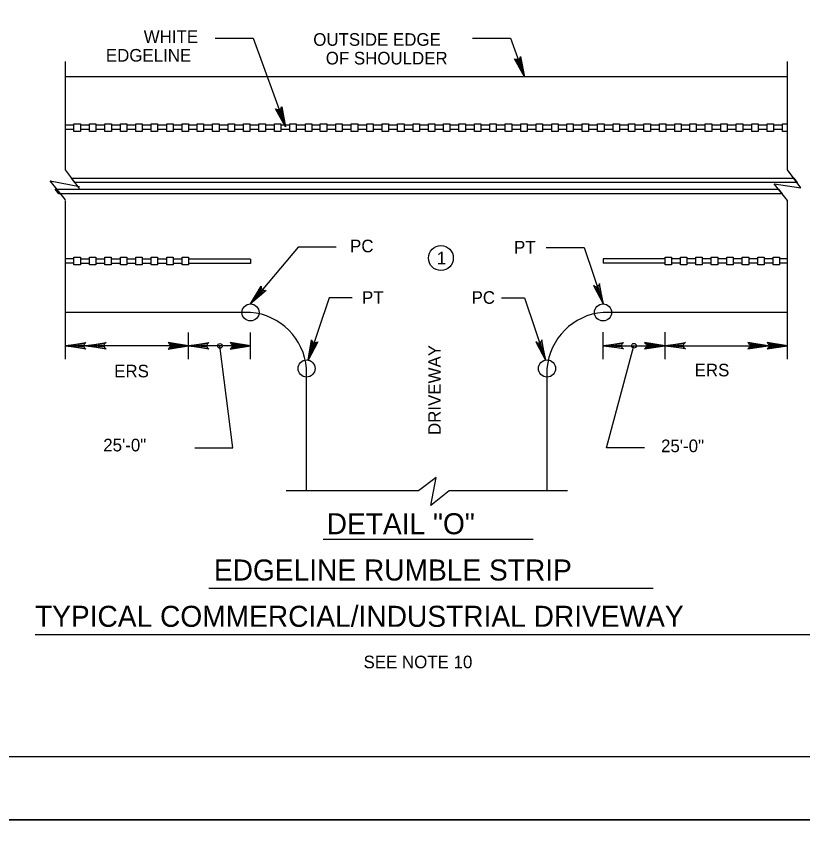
# Model space of a CAD drawing. Extents: x 632008 to 634206, y 294231 to 297795.
# Drawn here: x 632240.2 to 632427, y 296005.1 to 296203.4 of the extents above; entities that cross this region are included whole.
import ezdxf

# ---------------------------------------------------------------- set-up
doc = ezdxf.new("R2010")
doc.units = 0
for name, color, linetype in [('1', 7, 'Continuous'), ('3', 7, 'Continuous'), ('Level 2', 7, 'Continuous'), ('PLT-BNDY', 7, 'Continuous')]:
    doc.layers.add(name, color=color, linetype=linetype)

msp = doc.modelspace()

# ---------------------------------------------------------------- linework, layer by layer
at = {"layer": '1'}
for p, q in [((632295.81, 296145.82), (632295.81, 296144.8)), ((632379.61, 296145.91), (632379.61, 296144.9)), ((632313.08, 296079.29), (632362.95, 296079.29)), ((632285.89, 296067.61), (632391.48, 296067.61)), ((632244.66, 296056.61), (632433.76, 296056.61))]:
    msp.add_line(p, q, dxfattribs=at)
msp.add_lwpolyline([(632833.86, 296027.62), (632833.86, 296591.62), (632047.86, 296591.62), (632047.86, 296027.62), (632833.86, 296027.62), (632833.86, 296053.98), (632633.86, 296053.98), (632633.86, 296118.66), (632833.86, 296118.66), (632833.86, 296147.62), (632633.86, 296147.62), (632633.86, 296027.62), (632712.66, 296027.62), (632712.66, 296053.98), (632712.66, 296027.62), (632789.66, 296027.62), (632789.66, 296053.98), (632789.66, 296041.66), (632833.86, 296041.66)], dxfattribs=at)
for points in [[(632253.3, 296165.06), (632424.94, 296165.06), (632425.73, 296164), (632254.09, 296164)], [(632422.15, 296161.36), (632250.27, 296161.36), (632249.41, 296162.42), (632421.3, 296162.42)]]:
    msp.add_lwpolyline(points, close=True, dxfattribs=at)
at = {"layer": '3'}
for points in [[(632319.95, 296136.61), (632314.48, 296136.61), (632309.52, 296121.84)], [(632355.46, 296136.61), (632360.92, 296136.61), (632365.89, 296121.84)], [(632311.53, 296126.02), (632311.16, 296125.96), (632309.52, 296121.84), (632311.53, 296126.02), (632311.8, 296126.18), (632309.52, 296121.84), (632310.72, 296126.11), (632310.46, 296126.36), (632309.52, 296121.84), (632310.33, 296126.67), (632310.46, 296126.36)], [(632363.87, 296126.02), (632364.24, 296125.96), (632365.89, 296121.84), (632363.87, 296126.02), (632363.61, 296126.18), (632365.89, 296121.84), (632364.68, 296126.11), (632364.94, 296126.36), (632365.89, 296121.84), (632365.07, 296126.67), (632364.94, 296126.36)]]:
    msp.add_lwpolyline(points, dxfattribs=at)
for centre, radius in [((632341.06, 296146.08), 2.95), ((632309.13, 296119.85), 2.03), ((632366.28, 296119.85), 2.03)]:
    msp.add_circle(centre, radius, dxfattribs=at)
at = {"layer": 'Level 2'}
for p, q in [((632251.81, 296167.04), (632251.82, 296192.79)), ((632423.46, 296167.04), (632423.46, 296192.79)), ((632423.46, 296189.15), (632251.81, 296189.15)), ((632253.85, 296177.63), (632251.81, 296177.63)), ((632257.52, 296177.63), (632255.38, 296177.63)), ((632261.2, 296177.63), (632259.05, 296177.63)), ((632264.87, 296177.63), (632262.73, 296177.63)), ((632268.54, 296177.63), (632266.4, 296177.63)), ((632272.21, 296177.63), (632270.07, 296177.63)), ((632275.89, 296177.63), (632273.74, 296177.63)), ((632279.56, 296177.63), (632277.42, 296177.63)), ((632283.13, 296177.63), (632281.09, 296177.63)), ((632286.8, 296177.63), (632284.66, 296177.63)), ((632290.47, 296177.63), (632288.33, 296177.63)), ((632294.14, 296177.63), (632292, 296177.63)), ((632297.82, 296177.63), (632295.67, 296177.63)), ((632301.49, 296177.63), (632299.35, 296177.63)), ((632305.16, 296177.63), (632303.02, 296177.63)), ((632308.84, 296177.63), (632306.69, 296177.63)), ((632312.4, 296177.63), (632310.37, 296177.63)), ((632316.07, 296177.63), (632313.93, 296177.63)), ((632319.75, 296177.63), (632317.6, 296177.63)), ((632323.42, 296177.63), (632321.28, 296177.63)), ((632327.09, 296177.63), (632324.95, 296177.63)), ((632330.76, 296177.63), (632328.62, 296177.63)), ((632334.44, 296177.63), (632332.3, 296177.63)), ((632338.11, 296177.63), (632335.97, 296177.63)), ((632341.68, 296177.63), (632339.64, 296177.63)), ((632345.35, 296177.63), (632343.21, 296177.63)), ((632349.02, 296177.63), (632346.88, 296177.63)), ((632352.69, 296177.63), (632350.55, 296177.63)), ((632356.37, 296177.63), (632354.23, 296177.63)), ((632360.04, 296177.63), (632357.9, 296177.63)), ((632363.71, 296177.63), (632361.57, 296177.63)), ((632367.39, 296177.63), (632365.24, 296177.63)), ((632370.95, 296177.63), (632368.92, 296177.63)), ((632374.62, 296177.63), (632372.48, 296177.63)), ((632378.3, 296177.63), (632376.16, 296177.63)), ((632381.97, 296177.63), (632379.83, 296177.63)), ((632385.64, 296177.63), (632383.5, 296177.63)), ((632389.32, 296177.63), (632387.17, 296177.63)), ((632392.99, 296177.63), (632390.85, 296177.63)), ((632396.66, 296177.63), (632394.52, 296177.63)), ((632400.23, 296177.63), (632398.19, 296177.63)), ((632403.9, 296177.63), (632401.76, 296177.63)), ((632407.57, 296177.63), (632405.43, 296177.63)), ((632411.25, 296177.63), (632409.1, 296177.63)), ((632414.92, 296177.63), (632412.78, 296177.63)), ((632418.59, 296177.63), (632416.45, 296177.63)), ((632422.26, 296177.63), (632420.12, 296177.63)), ((632253.85, 296176.61), (632251.81, 296176.61)), ((632257.52, 296176.61), (632255.38, 296176.61)), ((632261.2, 296176.61), (632259.05, 296176.61)), ((632264.87, 296176.61), (632262.73, 296176.61)), ((632268.54, 296176.61), (632266.4, 296176.61)), ((632272.21, 296176.61), (632270.07, 296176.61)), ((632275.89, 296176.61), (632273.74, 296176.61)), ((632279.56, 296176.61), (632277.42, 296176.61)), ((632283.13, 296176.61), (632281.09, 296176.61)), ((632286.8, 296176.61), (632284.66, 296176.61)), ((632290.47, 296176.61), (632288.33, 296176.61)), ((632294.14, 296176.61), (632292, 296176.61)), ((632297.82, 296176.61), (632295.67, 296176.61)), ((632301.49, 296176.61), (632299.35, 296176.61)), ((632305.16, 296176.61), (632303.02, 296176.61)), ((632308.84, 296176.61), (632306.69, 296176.61)), ((632312.4, 296176.61), (632310.37, 296176.61)), ((632316.07, 296176.61), (632313.93, 296176.61)), ((632319.75, 296176.61), (632317.6, 296176.61)), ((632323.42, 296176.61), (632321.28, 296176.61)), ((632327.09, 296176.61), (632324.95, 296176.61)), ((632330.76, 296176.61), (632328.62, 296176.61)), ((632334.44, 296176.61), (632332.3, 296176.61)), ((632338.11, 296176.61), (632335.97, 296176.61)), ((632341.68, 296176.61), (632339.64, 296176.61)), ((632345.35, 296176.61), (632343.21, 296176.61)), ((632349.02, 296176.61), (632346.88, 296176.61)), ((632352.69, 296176.61), (632350.55, 296176.61)), ((632356.37, 296176.61), (632354.23, 296176.61)), ((632360.04, 296176.61), (632357.9, 296176.61)), ((632363.71, 296176.61), (632361.57, 296176.61)), ((632367.39, 296176.61), (632365.24, 296176.61)), ((632370.95, 296176.61), (632368.92, 296176.61)), ((632374.62, 296176.61), (632372.48, 296176.61)), ((632378.3, 296176.61), (632376.16, 296176.61)), ((632381.97, 296176.61), (632379.83, 296176.61)), ((632385.64, 296176.61), (632383.5, 296176.61)), ((632389.32, 296176.61), (632387.17, 296176.61)), ((632392.99, 296176.61), (632390.85, 296176.61)), ((632396.66, 296176.61), (632394.52, 296176.61)), ((632400.23, 296176.61), (632398.19, 296176.61)), ((632403.9, 296176.61), (632401.76, 296176.61)), ((632407.57, 296176.61), (632405.43, 296176.61)), ((632411.25, 296176.61), (632409.1, 296176.61)), ((632414.92, 296176.61), (632412.78, 296176.61)), ((632418.59, 296176.61), (632416.45, 296176.61)), ((632422.26, 296176.61), (632420.12, 296176.61)), ((632255.13, 296162.61), (632251.81, 296167.04)), ((632426.64, 296162.78), (632423.46, 296167.04)), ((632248.17, 296164.42), (632255.13, 296163.07)), ((632251.81, 296159.92), (632248.17, 296164.42)), ((632423.46, 296159.76), (632420.25, 296163.71)), ((632420.25, 296163.71), (632426.64, 296162.78)), ((632251.81, 296122.05), (632251.81, 296159.76)), ((632423.46, 296122.09), (632423.46, 296159.76)), ((632253.85, 296145.9), (632251.81, 296145.9)), ((632257.52, 296145.82), (632255.38, 296145.82)), ((632261.19, 296145.82), (632259.05, 296145.82)), ((632264.87, 296145.82), (632262.72, 296145.82)), ((632268.54, 296145.82), (632266.4, 296145.82)), ((632272.21, 296145.82), (632270.07, 296145.82)), ((632275.89, 296145.82), (632273.74, 296145.82)), ((632279.56, 296145.82), (632277.42, 296145.82)), ((632295.81, 296145.82), (632281.09, 296145.82)), ((632394.32, 296145.91), (632379.61, 296145.91)), ((632397.99, 296145.91), (632395.85, 296145.91)), ((632401.66, 296145.91), (632399.52, 296145.91)), ((632405.33, 296145.91), (632403.19, 296145.91)), ((632409.01, 296145.91), (632406.86, 296145.91)), ((632412.68, 296145.91), (632410.54, 296145.91)), ((632416.35, 296145.91), (632414.21, 296145.91)), ((632420.03, 296145.91), (632417.88, 296145.91)), ((632423.46, 296145.91), (632421.56, 296145.91)), ((632253.85, 296144.89), (632251.81, 296144.89)), ((632257.52, 296144.8), (632255.38, 296144.8)), ((632261.19, 296144.8), (632259.05, 296144.8)), ((632264.87, 296144.8), (632262.72, 296144.8)), ((632268.54, 296144.8), (632266.4, 296144.8)), ((632272.21, 296144.8), (632270.07, 296144.8)), ((632275.89, 296144.8), (632273.74, 296144.8)), ((632279.56, 296144.8), (632277.42, 296144.8)), ((632295.81, 296144.8), (632281.09, 296144.8)), ((632394.32, 296144.9), (632379.61, 296144.9)), ((632397.99, 296144.9), (632395.85, 296144.9)), ((632401.66, 296144.9), (632399.52, 296144.9)), ((632405.33, 296144.9), (632403.19, 296144.9)), ((632409.01, 296144.9), (632406.86, 296144.9)), ((632412.68, 296144.9), (632410.54, 296144.9)), ((632416.35, 296144.9), (632414.21, 296144.9)), ((632420.03, 296144.9), (632417.88, 296144.9)), ((632423.46, 296144.9), (632421.56, 296144.9)), ((632295.81, 296133.16), (632251.95, 296133.16)), ((632423.46, 296133.16), (632379.59, 296133.16)), ((632281.09, 296122.05), (632281.09, 296128.4)), ((632295.81, 296122.05), (632295.81, 296128.4)), ((632379.59, 296122.09), (632379.59, 296128.44)), ((632394.32, 296122.09), (632394.32, 296128.44)), ((632295.81, 296125.22), (632251.81, 296125.22)), ((632379.59, 296125.26), (632423.46, 296125.26)), ((632309.13, 296090.79), (632309.13, 296119.85)), ((632366.28, 296090.79), (632366.28, 296119.85)), ((632339.97, 296093.98), (632335.72, 296090.79)), ((632338.68, 296087.29), (632339.97, 296093.98)), ((632335.72, 296090.79), (632304.28, 296090.79)), ((632343, 296090.79), (632338.68, 296087.29)), ((632371.13, 296090.79), (632343, 296090.79))]:
    msp.add_line(p, q, dxfattribs=at)
for points in [[(632287.43, 296198.35), (632296.46, 296198.35), (632304.15, 296177.23)], [(632348.54, 296198.35), (632357.58, 296198.35), (632360.93, 296189.15)], [(632359.89, 296193.67), (632359.64, 296193.4), (632360.93, 296189.15), (632359.89, 296193.67), (632360, 296193.96), (632360.93, 296189.15), (632359.2, 296193.24), (632358.84, 296193.27), (632360.93, 296189.15), (632358.55, 296193.43), (632358.84, 296193.27)], [(632303.11, 296181.75), (632302.86, 296181.48), (632304.15, 296177.23), (632303.11, 296181.75), (632303.22, 296182.05), (632304.15, 296177.23), (632302.42, 296181.32), (632302.06, 296181.36), (632304.15, 296177.23), (632301.77, 296181.51), (632302.06, 296181.36)], [(632423.46, 296176.12), (632422.26, 296176.12), (632422.26, 296177.96), (632423.46, 296177.96)], [(632423.46, 296176.12), (632422.26, 296176.12), (632422.26, 296177.96), (632423.46, 296177.96)], [(632316.18, 296148.65), (632307.14, 296148.65), (632295.81, 296135.19)], [(632366.05, 296148.61), (632375.08, 296148.61), (632379.59, 296135.19)], [(632377.58, 296139.37), (632377.95, 296139.31), (632379.59, 296135.19), (632377.58, 296139.37), (632377.31, 296139.53), (632379.59, 296135.19), (632378.39, 296139.46), (632378.65, 296139.71), (632379.59, 296135.19), (632378.78, 296140.02), (632378.65, 296139.71)], [(632299.23, 296138.33), (632298.86, 296138.42), (632295.81, 296135.19), (632299.23, 296138.33), (632299.53, 296138.38), (632295.81, 296135.19), (632298.5, 296138.71), (632298.36, 296139.05), (632295.81, 296135.19), (632298.35, 296139.38), (632298.36, 296139.05)], [(632256.42, 296124.64), (632256.25, 296124.98), (632251.81, 296125.22), (632256.42, 296124.64), (632256.65, 296124.44), (632251.81, 296125.22), (632256.24, 296125.44), (632256.4, 296125.77), (632251.81, 296125.22), (632256.65, 296125.99), (632256.4, 296125.77)], [(632261.23, 296124.64), (632261.07, 296124.98), (632256.63, 296125.22), (632261.23, 296124.64), (632261.47, 296124.44), (632256.63, 296125.22), (632261.06, 296125.44), (632261.22, 296125.77), (632256.63, 296125.22), (632261.47, 296125.99), (632261.22, 296125.77)], [(632276.49, 296124.64), (632276.65, 296124.98), (632281.09, 296125.22), (632276.49, 296124.64), (632276.25, 296124.44), (632281.09, 296125.22), (632276.66, 296125.44), (632276.5, 296125.77), (632281.09, 296125.22), (632276.25, 296125.99), (632276.5, 296125.77)], [(632285.69, 296124.64), (632285.52, 296124.98), (632281.09, 296125.22), (632285.69, 296124.64), (632285.93, 296124.44), (632281.09, 296125.22), (632285.52, 296125.44), (632285.68, 296125.77), (632281.09, 296125.22), (632285.93, 296125.99), (632285.68, 296125.77)], [(632291.21, 296124.64), (632291.38, 296124.98), (632295.81, 296125.22), (632291.21, 296124.64), (632290.97, 296124.44), (632295.81, 296125.22), (632291.39, 296125.44), (632291.22, 296125.77), (632295.81, 296125.22), (632290.97, 296125.99), (632291.22, 296125.77)], [(632384.19, 296124.68), (632384.03, 296125.02), (632379.59, 296125.26), (632384.19, 296124.68), (632384.43, 296124.48), (632379.59, 296125.26), (632384.02, 296125.48), (632384.18, 296125.81), (632379.59, 296125.26), (632384.43, 296126.03), (632384.18, 296125.81)], [(632389.71, 296124.68), (632389.88, 296125.02), (632394.32, 296125.26), (632389.71, 296124.68), (632389.48, 296124.48), (632394.32, 296125.26), (632389.89, 296125.48), (632389.73, 296125.81), (632394.32, 296125.26), (632389.48, 296126.03), (632389.73, 296125.81)], [(632398.92, 296124.68), (632398.75, 296125.02), (632394.32, 296125.26), (632398.92, 296124.68), (632399.16, 296124.48), (632394.32, 296125.26), (632398.74, 296125.48), (632398.91, 296125.81), (632394.32, 296125.26), (632399.16, 296126.03), (632398.91, 296125.81)], [(632414.25, 296124.68), (632414.42, 296125.02), (632418.85, 296125.26), (632414.25, 296124.68), (632414.01, 296124.48), (632418.85, 296125.26), (632414.42, 296125.48), (632414.26, 296125.81), (632418.85, 296125.26), (632414.01, 296126.03), (632414.26, 296125.81)], [(632418.86, 296124.68), (632419.03, 296125.02), (632423.46, 296125.26), (632418.86, 296124.68), (632418.63, 296124.48), (632423.46, 296125.26), (632419.04, 296125.48), (632418.87, 296125.81), (632423.46, 296125.26), (632418.63, 296126.03), (632418.87, 296125.81)], [(632282.56, 296101.03), (632291.6, 296101.03), (632288.54, 296125.22)], [(632389.43, 296101.03), (632380.39, 296101.03), (632386.93, 296125.25)]]:
    msp.add_lwpolyline(points, dxfattribs=at)
for points in [[(632253.85, 296177.96), (632255.38, 296177.96), (632255.38, 296176.12), (632253.85, 296176.12)], [(632257.52, 296177.96), (632259.05, 296177.96), (632259.05, 296176.12), (632257.52, 296176.12)], [(632261.2, 296177.96), (632262.73, 296177.96), (632262.73, 296176.12), (632261.2, 296176.12)], [(632264.87, 296177.96), (632266.4, 296177.96), (632266.4, 296176.12), (632264.87, 296176.12)], [(632264.87, 296177.96), (632266.4, 296177.96), (632266.4, 296176.12), (632264.87, 296176.12)], [(632268.54, 296177.96), (632270.07, 296177.96), (632270.07, 296176.12), (632268.54, 296176.12)], [(632268.54, 296177.96), (632270.07, 296177.96), (632270.07, 296176.12), (632268.54, 296176.12)], [(632272.21, 296177.96), (632273.74, 296177.96), (632273.74, 296176.12), (632272.21, 296176.12)], [(632272.21, 296177.96), (632273.74, 296177.96), (632273.74, 296176.12), (632272.21, 296176.12)], [(632275.89, 296177.96), (632277.42, 296177.96), (632277.42, 296176.12), (632275.89, 296176.12)], [(632275.89, 296177.96), (632277.42, 296177.96), (632277.42, 296176.12), (632275.89, 296176.12)], [(632279.56, 296177.96), (632281.09, 296177.96), (632281.09, 296176.12), (632279.56, 296176.12)], [(632279.56, 296177.96), (632281.09, 296177.96), (632281.09, 296176.12), (632279.56, 296176.12)], [(632283.13, 296177.96), (632284.66, 296177.96), (632284.66, 296176.12), (632283.13, 296176.12)], [(632286.8, 296177.96), (632288.33, 296177.96), (632288.33, 296176.12), (632286.8, 296176.12)], [(632290.47, 296177.96), (632292, 296177.96), (632292, 296176.12), (632290.47, 296176.12)], [(632294.14, 296177.96), (632295.67, 296177.96), (632295.67, 296176.12), (632294.14, 296176.12)], [(632294.14, 296177.96), (632295.67, 296177.96), (632295.67, 296176.12), (632294.14, 296176.12)], [(632297.82, 296177.96), (632299.35, 296177.96), (632299.35, 296176.12), (632297.82, 296176.12)], [(632297.82, 296177.96), (632299.35, 296177.96), (632299.35, 296176.12), (632297.82, 296176.12)], [(632301.49, 296177.96), (632303.02, 296177.96), (632303.02, 296176.12), (632301.49, 296176.12)], [(632301.49, 296177.96), (632303.02, 296177.96), (632303.02, 296176.12), (632301.49, 296176.12)], [(632305.16, 296177.96), (632306.69, 296177.96), (632306.69, 296176.12), (632305.16, 296176.12)], [(632305.16, 296177.96), (632306.69, 296177.96), (632306.69, 296176.12), (632305.16, 296176.12)], [(632308.84, 296177.96), (632310.37, 296177.96), (632310.37, 296176.12), (632308.84, 296176.12)], [(632308.84, 296177.96), (632310.37, 296177.96), (632310.37, 296176.12), (632308.84, 296176.12)], [(632312.4, 296177.96), (632313.93, 296177.96), (632313.93, 296176.12), (632312.4, 296176.12)], [(632316.07, 296177.96), (632317.6, 296177.96), (632317.6, 296176.12), (632316.07, 296176.12)], [(632319.75, 296177.96), (632321.28, 296177.96), (632321.28, 296176.12), (632319.75, 296176.12)], [(632323.42, 296177.96), (632324.95, 296177.96), (632324.95, 296176.12), (632323.42, 296176.12)], [(632323.42, 296177.96), (632324.95, 296177.96), (632324.95, 296176.12), (632323.42, 296176.12)], [(632327.09, 296177.96), (632328.62, 296177.96), (632328.62, 296176.12), (632327.09, 296176.12)], [(632327.09, 296177.96), (632328.62, 296177.96), (632328.62, 296176.12), (632327.09, 296176.12)], [(632330.76, 296177.96), (632332.3, 296177.96), (632332.3, 296176.12), (632330.76, 296176.12)], [(632330.76, 296177.96), (632332.3, 296177.96), (632332.3, 296176.12), (632330.76, 296176.12)], [(632334.44, 296177.96), (632335.97, 296177.96), (632335.97, 296176.12), (632334.44, 296176.12)], [(632334.44, 296177.96), (632335.97, 296177.96), (632335.97, 296176.12), (632334.44, 296176.12)], [(632338.11, 296177.96), (632339.64, 296177.96), (632339.64, 296176.12), (632338.11, 296176.12)], [(632338.11, 296177.96), (632339.64, 296177.96), (632339.64, 296176.12), (632338.11, 296176.12)], [(632341.68, 296177.96), (632343.21, 296177.96), (632343.21, 296176.12), (632341.68, 296176.12)], [(632345.35, 296177.96), (632346.88, 296177.96), (632346.88, 296176.12), (632345.35, 296176.12)], [(632349.02, 296177.96), (632350.55, 296177.96), (632350.55, 296176.12), (632349.02, 296176.12)], [(632352.69, 296177.96), (632354.23, 296177.96), (632354.23, 296176.12), (632352.69, 296176.12)], [(632352.69, 296177.96), (632354.23, 296177.96), (632354.23, 296176.12), (632352.69, 296176.12)], [(632356.37, 296177.96), (632357.9, 296177.96), (632357.9, 296176.12), (632356.37, 296176.12)], [(632356.37, 296177.96), (632357.9, 296177.96), (632357.9, 296176.12), (632356.37, 296176.12)], [(632360.04, 296177.96), (632361.57, 296177.96), (632361.57, 296176.12), (632360.04, 296176.12)], [(632360.04, 296177.96), (632361.57, 296177.96), (632361.57, 296176.12), (632360.04, 296176.12)], [(632363.71, 296177.96), (632365.24, 296177.96), (632365.24, 296176.12), (632363.71, 296176.12)], [(632363.71, 296177.96), (632365.24, 296177.96), (632365.24, 296176.12), (632363.71, 296176.12)], [(632367.39, 296177.96), (632368.92, 296177.96), (632368.92, 296176.12), (632367.39, 296176.12)], [(632367.39, 296177.96), (632368.92, 296177.96), (632368.92, 296176.12), (632367.39, 296176.12)], [(632370.95, 296177.96), (632372.48, 296177.96), (632372.48, 296176.12), (632370.95, 296176.12)], [(632374.62, 296177.96), (632376.16, 296177.96), (632376.16, 296176.12), (632374.62, 296176.12)], [(632378.3, 296177.96), (632379.83, 296177.96), (632379.83, 296176.12), (632378.3, 296176.12)], [(632381.97, 296177.96), (632383.5, 296177.96), (632383.5, 296176.12), (632381.97, 296176.12)], [(632381.97, 296177.96), (632383.5, 296177.96), (632383.5, 296176.12), (632381.97, 296176.12)], [(632385.64, 296177.96), (632387.17, 296177.96), (632387.17, 296176.12), (632385.64, 296176.12)], [(632385.64, 296177.96), (632387.17, 296177.96), (632387.17, 296176.12), (632385.64, 296176.12)], [(632389.32, 296177.96), (632390.85, 296177.96), (632390.85, 296176.12), (632389.32, 296176.12)], [(632389.32, 296177.96), (632390.85, 296177.96), (632390.85, 296176.12), (632389.32, 296176.12)], [(632392.99, 296177.96), (632394.52, 296177.96), (632394.52, 296176.12), (632392.99, 296176.12)], [(632392.99, 296177.96), (632394.52, 296177.96), (632394.52, 296176.12), (632392.99, 296176.12)], [(632396.66, 296177.96), (632398.19, 296177.96), (632398.19, 296176.12), (632396.66, 296176.12)], [(632396.66, 296177.96), (632398.19, 296177.96), (632398.19, 296176.12), (632396.66, 296176.12)], [(632400.23, 296177.96), (632401.76, 296177.96), (632401.76, 296176.12), (632400.23, 296176.12)], [(632403.9, 296177.96), (632405.43, 296177.96), (632405.43, 296176.12), (632403.9, 296176.12)], [(632407.57, 296177.96), (632409.1, 296177.96), (632409.1, 296176.12), (632407.57, 296176.12)], [(632411.25, 296177.96), (632412.78, 296177.96), (632412.78, 296176.12), (632411.25, 296176.12)], [(632411.25, 296177.96), (632412.78, 296177.96), (632412.78, 296176.12), (632411.25, 296176.12)], [(632414.92, 296177.96), (632416.45, 296177.96), (632416.45, 296176.12), (632414.92, 296176.12)], [(632414.92, 296177.96), (632416.45, 296177.96), (632416.45, 296176.12), (632414.92, 296176.12)], [(632418.59, 296177.96), (632420.12, 296177.96), (632420.12, 296176.12), (632418.59, 296176.12)], [(632418.59, 296177.96), (632420.12, 296177.96), (632420.12, 296176.12), (632418.59, 296176.12)], [(632253.85, 296146.28), (632255.38, 296146.28), (632255.38, 296144.44), (632253.85, 296144.44)], [(632257.52, 296146.28), (632259.05, 296146.28), (632259.05, 296144.44), (632257.52, 296144.44)], [(632261.19, 296146.28), (632262.72, 296146.28), (632262.72, 296144.44), (632261.19, 296144.44)], [(632264.87, 296146.28), (632266.4, 296146.28), (632266.4, 296144.44), (632264.87, 296144.44)], [(632268.54, 296146.28), (632270.07, 296146.28), (632270.07, 296144.44), (632268.54, 296144.44)], [(632272.21, 296146.28), (632273.74, 296146.28), (632273.74, 296144.44), (632272.21, 296144.44)], [(632275.89, 296146.28), (632277.42, 296146.28), (632277.42, 296144.44), (632275.89, 296144.44)], [(632279.56, 296146.28), (632281.09, 296146.28), (632281.09, 296144.44), (632279.56, 296144.44)], [(632394.32, 296146.28), (632395.85, 296146.28), (632395.85, 296144.44), (632394.32, 296144.44)], [(632397.99, 296146.28), (632399.52, 296146.28), (632399.52, 296144.44), (632397.99, 296144.44)], [(632401.66, 296146.28), (632403.19, 296146.28), (632403.19, 296144.44), (632401.66, 296144.44)], [(632405.33, 296146.28), (632406.86, 296146.28), (632406.86, 296144.44), (632405.33, 296144.44)], [(632409.01, 296146.28), (632410.54, 296146.28), (632410.54, 296144.44), (632409.01, 296144.44)], [(632412.68, 296146.28), (632414.21, 296146.28), (632414.21, 296144.44), (632412.68, 296144.44)], [(632416.35, 296146.28), (632417.88, 296146.28), (632417.88, 296144.44), (632416.35, 296144.44)], [(632420.03, 296146.28), (632421.56, 296146.28), (632421.56, 296144.44), (632420.03, 296144.44)]]:
    msp.add_lwpolyline(points, close=True, dxfattribs=at)
for centre, radius in [((632295.81, 296133.16), 2.03), ((632379.59, 296133.16), 2.03), ((632288.54, 296125.22), 0.558), ((632386.93, 296125.25), 0.558)]:
    msp.add_circle(centre, radius, dxfattribs=at)
for centre, start, end in [((632294.58, 296118.62), 4.837, 85.163), ((632380.82, 296118.62), 94.837, 175.163)]:
    msp.add_arc(centre, 14.6, start, end, dxfattribs=at)
at = {"layer": 'PLT-BNDY'}
for points in [[(632007.86, 296606.62), (632848.86, 296606.62), (632848.86, 296012.62), (632007.86, 296012.62)], [(632007.86, 296012.62), (632848.86, 296012.62), (632848.86, 295418.62), (632007.86, 295418.62)]]:
    msp.add_lwpolyline(points, close=True, dxfattribs=at)

# ---------------------------------------------------------------- texts
at = {"layer": '3'}
for s, p in [('PT', (632322.31, 296135.21)), ('PC', (632348.35, 296135.21))]:
    msp.add_text(s, height=3, dxfattribs=at).set_placement(p)
at = {"layer": 'Level 2'}
for s, height, p in [('WHITE', 3, (632270.43, 296197.2)), ('OUTSIDE EDGE', 3, (632310.72, 296196.52)), ('EDGELINE', 3, (632261.43, 296192.76)), ('OF SHOULDER', 3, (632313.69, 296192.08)), ('PC', 3, (632319.47, 296147.45)), ('PT', 3, (632358.44, 296147.15)), ('1', 3, (632340.09, 296144.58)), ('ERS', 3, (632263.41, 296117.74)), ('ERS', 3, (632401.36, 296117.97)), ('25\'-0"', 3, (632260.81, 296100.15)), ('25\'-0"', 3, (632393.38, 296099.96)), ('DETAIL "O"', 5, (632313.91, 296080.46)), ('EDGELINE RUMBLE STRIP', 5, (632287.1, 296069.46)), ('TYPICAL COMMERCIAL/INDUSTRIAL DRIVEWAY', 5, (632244.58, 296058.46)), ('SEE NOTE 10', 3, (632322.67, 296048.61))]:
    msp.add_text(s, height=height, dxfattribs=at).set_placement(p)
msp.add_text('DRIVEWAY', height=3, rotation=90, dxfattribs=at).set_placement((632341.04, 296104.03))

doc.saveas('drawing.dxf')
